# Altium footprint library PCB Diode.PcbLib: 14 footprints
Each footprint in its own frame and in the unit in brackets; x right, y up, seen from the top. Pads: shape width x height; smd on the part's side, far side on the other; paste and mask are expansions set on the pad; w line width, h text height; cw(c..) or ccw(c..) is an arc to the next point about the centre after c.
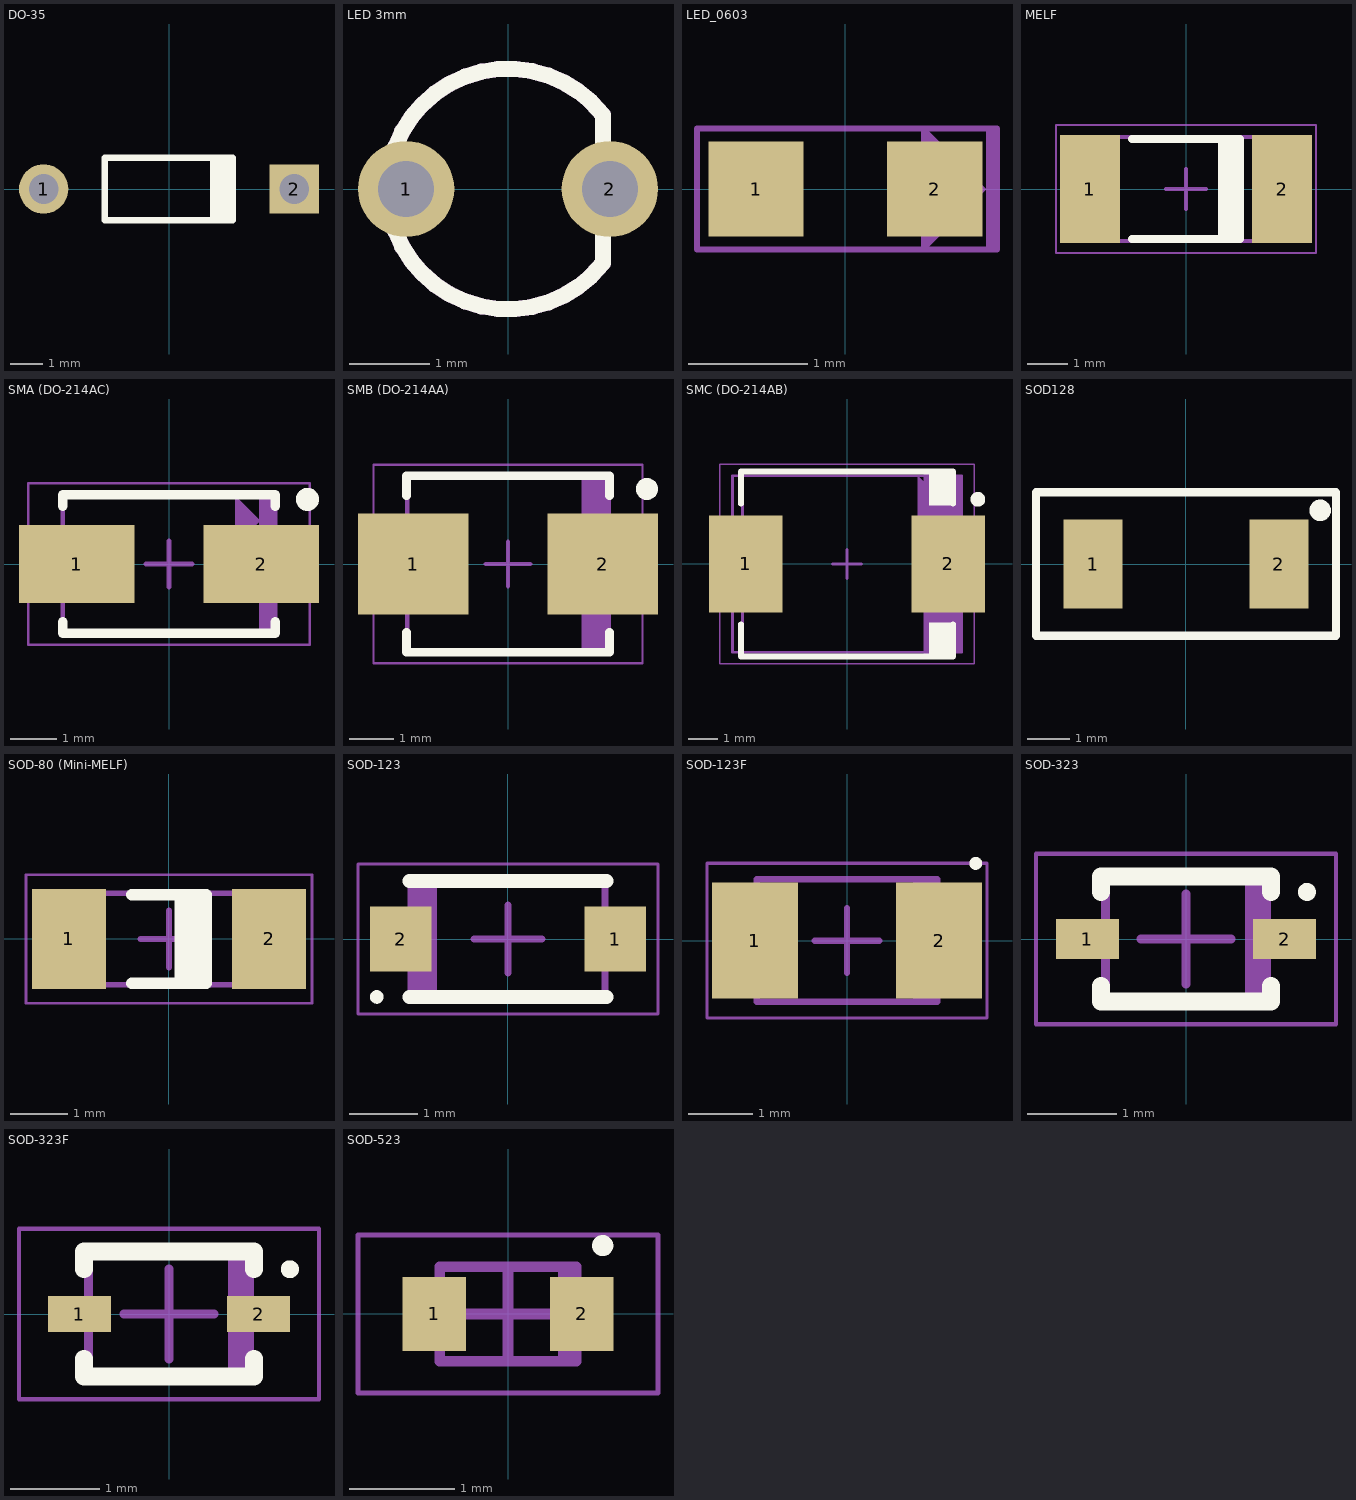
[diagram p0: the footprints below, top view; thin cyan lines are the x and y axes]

## DO-35 [mm]
pads (2):
  round 1.5 hole 0.9: 1(-3.81,0)
  rect 1.5x1.5 hole 0.9: 2(3.81,0)
Top Overlay:
  rectangle: 1.244,-0.95 2.044,0.95
  lines w0.2: 1.944,-0.95 -1.956,-0.95 -1.956,0.95 1.944,0.95
3D body "DO-204AH-RED.stp": height 2.1, standoff -2.5, extent -4.084,-1.016 4.084,0.976

## LED 3mm [mm] "THT LED 3mm, 2.54 pitch"
height 5
pads (2):
  round 1.2 hole 0.7: 1(-1.27,0) 2(1.27,0)
Top Overlay:
  lines w0.2: 1.184,-0.921 cw(c0,0) 1.184,0.921 1.184,-0.921
Mechanical 13:
  lines w0.2: 1.184,-0.921 cw(c0,0) 1.184,0.921 1.184,-0.921

## LED_0603 [mm]
pads (2):
  rect 0.8x0.8 smd: 1(-0.75,0) 2(0.75,0)
TopAsm:
  region: 1.27,0.508 1.27,-0.508 1.182,-0.508 1.182,0.508
  region: 1.182,0 0.674,0.508 0.635,0.508 0.635,-0.508 0.674,-0.508
  lines w0.051: -1.245,-0.508 -1.245,0.508 1.27,0.508 1.27,-0.508 -1.245,-0.508
  text ".Designator" at -1.067,-0.203 h0.51
3D body "User Library-LED SMD0603.step": height 0.68, standoff 0, extent -0.8,-0.375 0.85,0.35

## MELF [mm] "MELF Diode, 2-Leads, Body 5,00x2,50mm"
height 2.6
pads (2):
  rect 1.5x2.7 smd: 1(-2.4,0) 2(2.4,0)
Top Overlay:
  rectangle: 0.8,-1.25 1.35,1.25
  lines w0.2: -1.35,-1.25 1.35,-1.25 1.35,1.25 -1.35,1.25
Mechanical 13:
  lines w0.1: -2.6,-1.3 2.6,-1.3 2.6,1.3 -2.6,1.3 -2.6,-1.3
Mechanical 15:
  lines w0.05: -3.25,-1.6 3.25,-1.6 3.25,1.6 -3.25,1.6 -3.25,-1.6
  lines w0.1: -0.5,0 0.5,0 ; 0,-0.5 0,0.5
3D body: height 2.59, standoff 0, extent 2.05,-1.3 2.6,1.295
3D body: height 2.57, standoff 0.05, extent -2.05,-1.27 2.05,1.265
3D body: height 2.58, standoff 0.04, extent 0.85,-1.271 1.45,1.266
3D body: height 2.59, standoff 0, extent -2.6,-1.3 -2.05,1.295

## SMA (DO-214AC) [mm] "Molded Diode, 2-Leads, Body 4,30x2,60mm"
height 2.3
pads (2):
  rect 2.5x1.7 smd: 1(-2,0) 2(2,0)
Top Overlay:
  circle w0.25: c3,1.4 r0.125
  lines w0.2: -2.3,-1.25 -2.3,-1.5 2.3,-1.5 2.3,-1.25 ; -2.3,1.25 -2.3,1.5 2.3,1.5 2.3,1.25
Mechanical 15:
  lines w0.05: -3.05,-1.75 -3.05,1.75 3.05,1.75 3.05,-1.75 -3.05,-1.75
  lines w0.1: -0.5,0 0.5,0 ; 0,-0.5 0,0.5
TopAsm:
  region: 1.981,0.94 1.473,1.448 1.434,1.448 1.434,0.432 1.473,0.432
  region: 2.3,1.46 2.3,-1.46 1.958,-1.46 1.958,1.46
  lines w0.1: -2.3,-1.46 2.3,-1.46 2.3,1.46 -2.3,1.46 -2.3,-1.46
  text ".Designator" at -1.905,-0.787 h0.8
3D body "User Library-DO-214AC_SMA.step": height 2.15, standoff -0.05, extent -2.5,-1.35 2.5,1.35
3D body: height 0.79, standoff -0.33, extent 0.1,-3.3 0.1,-3.3

## SMB (DO-214AA) [mm] "Molded Diode, 2-Leads, Body 4,31x3,62mm"
height 2.5
pads (2):
  rect 2.5x2.3 smd: 1(-2.15,0) 2(2.15,0)
Top Overlay:
  circle w0.25: c3.15,1.7 r0.125
  lines w0.2: -2.3,-1.55 -2.3,-2 2.3,-2 2.3,-1.55 ; -2.3,1.55 -2.3,2 2.3,2 2.3,1.55
Mechanical 13:
  rectangle: 1.67,-1.97 2.285,1.97
  lines w0.1: -2.285,-1.97 2.285,-1.97 2.285,1.97 -2.285,1.97 -2.285,-1.97
Mechanical 15:
  lines w0.05: -3.05,-2.25 3.05,-2.25 3.05,2.25 -3.05,2.25 -3.05,-2.25
  lines w0.1: -0.5,0 0.5,0 ; 0,-0.5 0,0.5
3D body: height 2.5, standoff 0, extent -2.285,-1.97 2.285,1.97

## SMC (DO-214AB) [mm] "Molded Diode, 2-Leads, Body 6,85x5,90mm"
height 2.5
pads (2):
  rect 2.5x3.3 smd: 1(-3.45,0) 2(3.45,0)
Top Overlay:
  circle w0.25: c4.45,2.2 r0.125
  region: 3.6,2 2.8,2 2.8,3.15 3.6,3.15
  region: 3.6,-2 2.8,-2 2.8,-3.15 3.6,-3.15
  lines w0.2: -3.6,-2.05 -3.6,-3.15 3.6,-3.15 3.6,-2.05 ; -3.6,2.05 -3.6,3.15 3.6,3.15 3.6,2.05
Mechanical 13:
  rectangle: 2.599,-3.11 3.555,3.11
  lines w0.1: -3.555,-3.11 3.555,-3.11 3.555,3.11 -3.555,3.11 -3.555,-3.11
Mechanical 15:
  lines w0.05: -4.325,-3.4 4.325,-3.4 4.325,3.4 -4.325,3.4 -4.325,-3.4
  lines w0.1: -0.5,0 0.5,0 ; 0,-0.5 0,0.5
TopAsm:
  region: 3.9,3 3.9,-3 3.3,-3 3.3,3
  region: 3.308,2.1 2.4,3.008 2.4,1.192
  lines w0.1: -3.9,-3 -3.9,3 3.9,3 3.9,-3 -3.9,-3
  text ".Designator" at -3,-0.2 h1.2
3D body "User Library-DO-214AB-SMC.step": height 2.4, standoff -0.05, extent -3.9,-2.95 3.9,2.95

## SOD128 [mm]
pads (2):
  rect 1.4x2.1 smd: 1(-2.2,0) 2(2.2,0)
Top Overlay:
  circle w0.254: c3.175,1.27 r0.127
  lines w0.2: -3.55,-1.7 -3.55,0 -3.55,1.7 3.55,1.7 3.55,-1.7 -3.55,-1.7

## SOD-80 (Mini-MELF) [mm] "MELF Diode, 2-Leads, Body 3,50x1,45mm"
height 1.6
pads (2):
  rect 1.3x1.75 smd: 1(-1.75,0) 2(1.75,0)
Top Overlay:
  rectangle: 0.1,-0.775 0.65,0.775
  lines w0.2: -0.65,-0.775 0.65,-0.775 0.65,0.775 -0.65,0.775
Mechanical 13:
  lines w0.1: -1.85,-0.8 1.85,-0.8 1.85,0.8 -1.85,0.8 -1.85,-0.8
Mechanical 15:
  lines w0.05: -2.5,-1.125 2.5,-1.125 2.5,1.125 -2.5,1.125 -2.5,-1.125
  lines w0.1: -0.5,0 0.5,0 ; 0,-0.5 0,0.5
3D body: height 1.59, standoff 0, extent 1.35,-0.8 1.85,0.797
3D body: height 1.58, standoff 0.04, extent -1.35,-0.77 1.35,0.767
3D body: height 1.58, standoff 0.04, extent 0.15,-0.771 0.75,0.768
3D body: height 1.59, standoff 0, extent -1.85,-0.8 -1.35,0.797

## SOD-123 [mm] "Molded Diode, 2-Leads, Body 2,70x1,55mm"
height 1.35
pads (2):
  rect 0.9x0.95 smd: 1(1.575,0) 2(-1.575,0)
Top Overlay:
  circle w0.1: c-1.925,-0.85 r0.05
  lines w0.2: -1.45,-0.85 1.45,-0.85 ; -1.45,0.85 1.45,0.85
Mechanical 13:
  region: -1.042,0.85 -1.425,0.85 -1.425,-0.85 -1.042,-0.85
  lines w0.1: -1.425,-0.85 -1.425,0.85 1.425,0.85 1.425,-0.85 -1.425,-0.85
Mechanical 15:
  lines w0.05: -2.2,-1.1 -2.2,1.1 2.2,1.1 2.2,-1.1 -2.2,-1.1
  lines w0.1: -0.5,0 0.5,0 ; 0,-0.5 0,0.5
TopAsm:
  region: -1.042,0.85 -1.425,0.85 -1.425,-0.85 -1.042,-0.85
  lines w0.1: -1.425,-0.85 1.425,-0.85 1.425,0.85 -1.425,0.85 -1.425,-0.85
3D body "SOD-123.step": height 1.42, standoff -0.03, extent -1.925,-0.85 1.925,0.85

## SOD-123F [mm] "Molded Diode, 2-Leads, Body 2,70x1,80mm"
height 1.15
pads (2):
  rect 1.34x1.8 smd: 1(-1.43,0) 2(1.43,0)
Top Overlay:
  circle w0.1: c2,1.2 r0.05
Mechanical 13:
  rectangle: 1.023,-0.95 1.4,0.95
  lines w0.1: -1.4,-0.95 -1.4,0.95 1.4,0.95 1.4,-0.95 -1.4,-0.95
Mechanical 15:
  lines w0.05: -2.175,-1.2 -2.175,1.2 2.175,1.2 2.175,-1.2 -2.175,-1.2
  lines w0.1: -0.5,0 0.5,0 ; 0,-0.5 0,0.5
3D body: height 1.15, standoff 0, extent -1.4,-0.95 1.4,0.95

## SOD-323 [mm] "Molded Diode, 2-Leads, Body 1,70x1,30mm"
height 1.1
pads (2):
  rect 0.7x0.45 smd: 1(-1.1,0) 2(1.1,0)
Top Overlay:
  circle w0.1: c1.35,0.525 r0.05
  lines w0.2: -0.95,-0.525 -0.95,-0.7 0.95,-0.7 0.95,-0.525 ; -0.95,0.525 -0.95,0.7 0.95,0.7 0.95,0.525
Mechanical 13:
  rectangle: 0.658,-0.7 0.9,0.7
  lines w0.1: -0.9,-0.7 -0.9,0.7 0.9,0.7 0.9,-0.7 -0.9,-0.7
Mechanical 15:
  lines w0.05: -1.675,-0.95 -1.675,0.95 1.675,0.95 1.675,-0.95 -1.675,-0.95
  lines w0.1: -0.5,0 0.5,0 ; 0,-0.5 0,0.5
3D body "User Library-SOD-323.step": height 1.1, standoff 0, extent -1.3,-0.675 1.3,0.675

## SOD-323F [mm] "Molded Diode, 2-Leads, Body 1,70x1,25mm"
height 0.75
pads (2):
  rect 0.7x0.4 smd: 1(-1,0) 2(1,0)
Top Overlay:
  circle w0.1: c1.35,0.5 r0.05
  lines w0.2: -0.95,-0.5 -0.95,-0.7 0.95,-0.7 0.95,-0.5 ; -0.95,0.5 -0.95,0.7 0.95,0.7 0.95,0.5
Mechanical 13:
  rectangle: 0.658,-0.675 0.9,0.675
  lines w0.1: -0.9,-0.675 -0.9,0.675 0.9,0.675 0.9,-0.675 -0.9,-0.675
Mechanical 15:
  lines w0.05: -1.675,-0.95 -1.675,0.95 1.675,0.95 1.675,-0.95 -1.675,-0.95
  lines w0.1: -0.5,0 0.5,0 ; 0,-0.5 0,0.5
3D body: height 0.75, standoff 0, extent -0.9,-0.675 0.9,0.675

## SOD-523 [mm] "Molded Diode, 2-Leads, Body 1,20x0,80mm"
height 0.65
pads (2):
  rect 0.6x0.7 smd: 1(-0.7,0) 2(0.7,0)
Top Overlay:
  circle w0.1: c0.9,0.65 r0.05
Mechanical 13:
  rectangle: 0.475,-0.45 0.65,0.45
  lines w0.1: -0.65,-0.45 0.65,-0.45 0.65,0.45 -0.65,0.45 -0.65,-0.45
Mechanical 15:
  lines w0.05: -1.425,-0.75 1.425,-0.75 1.425,0.75 -1.425,0.75 -1.425,-0.75
  lines w0.1: -0.45,0 0.45,0 ; 0,-0.45 0,0.45
3D body: height 0.65, standoff 0, extent -0.65,-0.45 0.65,0.45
